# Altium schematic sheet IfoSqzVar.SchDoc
size A; DocumentNumber: 3; SheetNumber: 3; SheetTotal: 10; pInstance: Corner
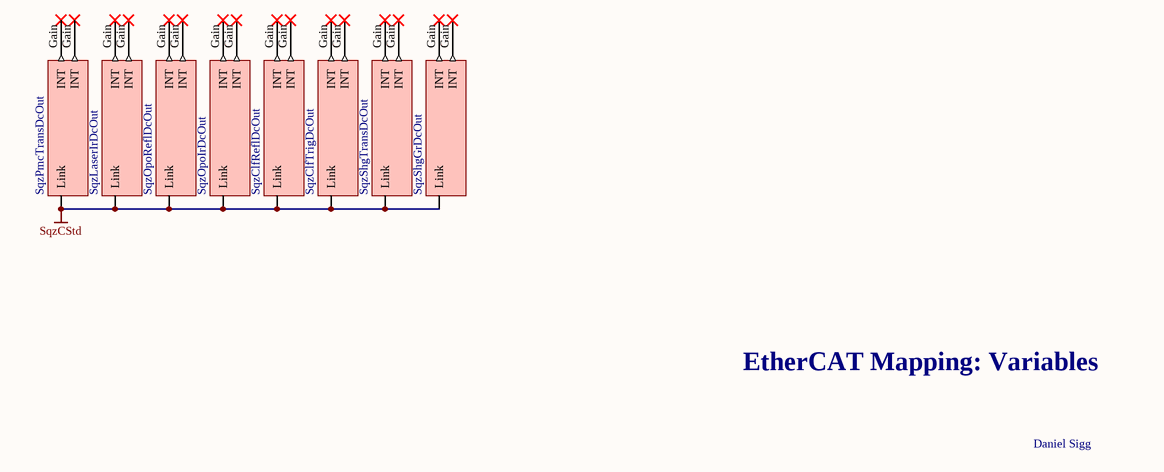
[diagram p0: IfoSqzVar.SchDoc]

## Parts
V66  SqzLaserIrDcOut  (no BOM)
V67  SqzPmcTransDcOut  (no BOM)
V69  SqzOpoReflDcOut  (no BOM)
V70  SqzOpoIrDcOut  (no BOM)
V71  SqzClfReflDcOut  (no BOM)
V72  SqzClfTrigDcOut  (no BOM)
V73  SqzShgTransDcOut  (no BOM)
V77  SqzShgGrDcOut  (no BOM)

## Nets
SqzCStd: V66.0(Link) V67.0(Link) V69.0(Link) V70.0(Link) V71.0(Link) V72.0(Link) V73.0(Link) V77.0(Link)

Not connected (* = marked no-connect by the designer): V66 Gain(INT)*; V67 Gain(INT)*; V69 Gain(INT)*; V70 Gain(INT)*; V71 Gain(INT)*; V72 Gain(INT)*; V73 Gain(INT)*; V77 Gain(INT)*

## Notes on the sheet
- EtherCAT Mapping: Variables
- Daniel Sigg

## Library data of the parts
V66 V67 V69-V73 V77 = DCPower_DCPowerOutStruct: DCPowerOutStruct; BoxType: Variable; Instance: H1SqzCorner Instance; PLC: H1SqzCorner; Task: SqzCStd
